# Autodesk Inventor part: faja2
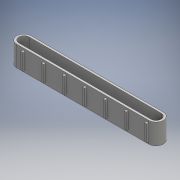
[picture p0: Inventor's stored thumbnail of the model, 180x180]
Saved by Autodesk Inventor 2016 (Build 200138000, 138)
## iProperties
Created: 2016-06
Part Number: faja2
Material: Generic
Document SubType Name: Modeling
Designer: yesi alvarez
Mass: 197.562 g
Surface Area: 870.673 cm^2
Volume: 197.562 cm^3
Density: 1 g/cm^3
Appearance: Default
Author: yesi alvarez
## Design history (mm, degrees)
sketch "Sketch1"
  geometry: L1 (0, 12.5)-(320, 12.5); L2 (0, -12.5)-(320, -12.5); L3 (320, 17.5)-(0, 17.5); L4 (0, -17.5)-(320, -17.5); A1 r 12.5 centre (0, 0) between (0, 12.5) and (0, -12.5); A2 r 12.5 centre (320, 0) between (320, -12.5) and (320, 12.5); A3 r 17.5 centre (0, 0) between (0, 17.5) and (0, -17.5); A4 r 17.5 centre (320, 0) between (320, -17.5) and (320, 17.5); 1 further point
  constraints: 8 end point, 8 point on circle, 4 centre point, 2 tangent, 1 coincident, 3 other
  dimensions: "d0" = 25 diameter of A1; "d2" = 25 diameter of A2; "d3" = 5 distance between parallel lines of L1 L3
extrude "Extrusion1" new body sketch "Sketch1" distance "d4" = 50; taper "d5" = 0 deg
sketch "Sketch2"
  geometry: L1 (10, -45)-(15, -45); L2 (15, -45)-(15, -5); L3 (15, -5)-(10, -5); L4 (10, -5)-(10, -45); L5 (60, -45)-(65, -45); L6 (65, -45)-(65, -5); L7 (65, -5)-(60, -5); L8 (60, -5)-(60, -45); L9 (110, -45)-(115, -45); L10 (115, -45)-(115, -5); L11 (115, -5)-(110, -5); L12 (110, -5)-(110, -45); L13 (160, -45)-(165, -45); L14 (165, -45)-(165, -5); L15 (165, -5)-(160, -5); L16 (160, -5)-(160, -45); L17 (210, -45)-(215, -45); L18 (215, -45)-(215, -5); L19 (215, -5)-(210, -5); L20 (210, -5)-(210, -45); L21 (260, -45)-(265, -45); L22 (265, -45)-(265, -5); L23 (265, -5)-(260, -5); L24 (260, -5)-(260, -45); L25 (310, -45)-(315, -45); L26 (315, -45)-(315, -5); L27 (315, -5)-(310, -5); L28 (310, -5)-(310, -45); 8 further points
  constraints: 56 end point, 14 parallel, 7 horizontal, 7 perpendicular, 1 coincident
  dimensions: "d6" = 10 horizontal distance of L1.start point (0, 0); "d7" = 50 distance of point (60, -45) L1.start; "d8" = 50 distance of point (110, -45) point (60, -45); "d9" = 50 distance of point (160, -45) point (110, -45); "d10" = 50 distance of point (210, -45) point (160, -45); "d11" = 50 distance of point (260, -45) point (210, -45); "d12" = 50 distance of point (310, -45) point (260, -45); "d13" = 45 vertical distance of L1.start point (0, 0); "d14" = 5 distance of L3.end L2.end; "d15" = 40 distance of L2.end L1.end; "d16" = 5 distance of L7.end L6.end; "d17" = 40 distance of L6.end L5.end; "d18" = 5 distance of L11.end L10.end; "d19" = 40 distance of L10.end L9.end; "d20" = 5 distance of L15.end L14.end; "d21" = 40 distance of L14.end L13.end; "d22" = 5 distance of L19.end L18.end; "d23" = 40 distance of L18.end L17.end; "d24" = 5 distance of L23.end L22.end; "d25" = 40 distance of L22.end L21.end; "d26" = 5 distance of L27.end L26.end; "d27" = 40 distance of L26.end L25.end
extrude "Extrusion2" join sketch "Sketch2" distance "d28" = 5; taper "d29" = 0 deg
workplane "Work Plane1"
sketch "Sketch5"
  geometry: L1 (15, 45)-(15, 5) reference; L2 (15, 5)-(20, 5); L3 (20, 5)-(20, 45); L4 (20, 45)-(15, 45); L5 (15, 45)-(15, 5); L6 (65, 5)-(70, 5); L7 (70, 5)-(70, 45); L8 (70, 45)-(65, 45); L9 (65, 45)-(65, 5); L10 (115, 5)-(120, 5); L11 (120, 5)-(120, 45); L12 (120, 45)-(115, 45); L13 (115, 45)-(115, 5); L14 (165, 5)-(170, 5); L15 (170, 5)-(170, 45); L16 (170, 45)-(165, 45); L17 (165, 45)-(165, 5); L18 (215, 5)-(220, 5); L19 (220, 5)-(220, 45); L20 (220, 45)-(215, 45); L21 (215, 45)-(215, 5); L22 (265, 45)-(265, 5); L23 (270, 5)-(270, 45); L24 (270, 45)-(265, 45); L25 (265, 5)-(270, 5); L26 (315, 45)-(315, 5); L27 (320, 5)-(320, 45); L28 (320, 45)-(315, 45); L29 (315, 5)-(320, 5); 1 further point
  constraints: 56 end point, 14 parallel, 7 horizontal, 7 perpendicular
  dimensions: "d30" = 5 distance of L4.end L3.end; "d31" = 40 distance of L3.end L2.end; "d41" = 40 distance of L15.end L14.end; "d45" = 40 distance of L19.end L18.end; "d46" = 50 distance between parallel lines of L9 L1; "d47" = 50 distance between parallel lines of L13 L9; "d48" = 50 distance between parallel lines of L17 L13; "d49" = 50 distance between parallel lines of L21 L17; "d50" = 40 distance of L23.end L23.start; "d51" = 40 distance of L27.end L27.start; "d52" = 50 distance between parallel lines of L22 L21; "d53" = 50 distance between parallel lines of L26 L22
extrude "Extrusion3" join sketch "Sketch5" distance "d54" = 5; taper "d55" = 0 deg
body "Solid1"
